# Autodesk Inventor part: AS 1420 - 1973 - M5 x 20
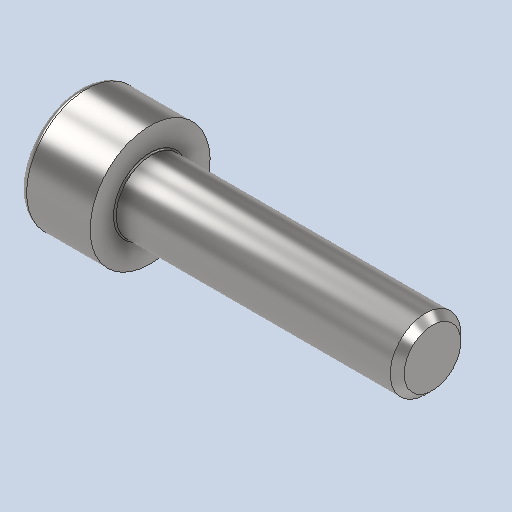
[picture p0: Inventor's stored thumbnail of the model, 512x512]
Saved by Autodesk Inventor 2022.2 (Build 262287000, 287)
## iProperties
Created: 2024-01
Part Number: AS 1420 - 1973 - M5 x 20
Material: Acciaio, Dolce
Document SubType Name: Modeling
Designer: 18907419
Density: 7.85 g/cm^3
Appearance: Default
Author: 18907419
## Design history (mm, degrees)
feature "Solid1"
node "Solido1"
